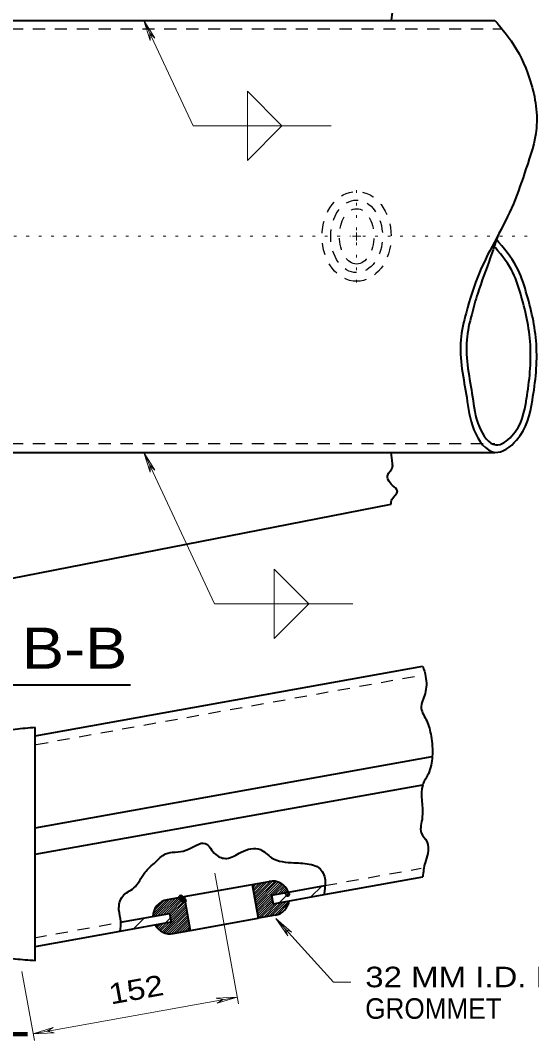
# Model space of a CAD drawing. Extents: x 312583 to 312854, y 144419 to 144597.
# Drawn here: x 312648.02 to 312666.93, y 144529.59 to 144567.31 of the extents above; entities that cross this region are included whole.
import ezdxf

# ---------------------------------------------------------------- set-up
doc = ezdxf.new("R2010")
doc.units = 0
doc.header["$LTSCALE"] = 0.3
doc.header["$PDMODE"] = 32
doc.header["$PDSIZE"] = 0.15
doc.linetypes.add('DOTTED', pattern=[1.5, 0.3, -1.2])
doc.linetypes.add('SHORT_DASHED', pattern=[2.7, 1.5, -1.2])
doc.layers.add('1', color=7, linetype='Continuous', lineweight=35)
doc.layers.add('2', color=7, linetype='Continuous', lineweight=13)

msp = doc.modelspace()

# ---------------------------------------------------------------- linework, layer by layer
at = {"layer": '1', "lineweight": 40}
for p, q in [((312647.674, 144567.3086), (312665.568, 144567.3086)), ((312647.674, 144551.3389), (312665.568, 144551.3389)), ((312647.674, 144546.6776), (312661.7347, 144549.4223)), ((312648.571, 144540.8586), (312662.9, 144543.4346)), ((312648.571, 144532.5403), (312648.571, 144541.1653)), ((312648.571, 144537.4546), (312663.2527, 144540.0919)), ((312648.571, 144536.4809), (312662.9, 144539.0493)), ((312656.5903, 144535.3616), (312657.219, 144535.4766)), ((312659.2507, 144534.9936), (312662.9, 144535.6453)), ((312654.0757, 144534.9169), (312656.5903, 144535.3616)), ((312656.5903, 144535.3616), (312656.8203, 144534.1119)), ((312657.311, 144534.9629), (312657.932, 144535.0779)), ((312657.932, 144535.0779), (312659.2813, 144535.3233)), ((312654.0757, 144534.9093), (312653.447, 144534.7943)), ((312654.0757, 144534.9169), (312654.3057, 144533.6596)), ((312657.311, 144534.9629), (312657.3723, 144534.6486)), ((312657.3723, 144534.6486), (312659.2507, 144534.9859)), ((312651.7297, 144533.9663), (312653.539, 144534.2883)), ((312653.539, 144534.2883), (312653.6003, 144533.9739)), ((312651.7067, 144533.6366), (312653.6003, 144533.9739)), ((312654.3057, 144533.6596), (312656.8203, 144534.1119)), ((312657.449, 144534.2269), (312656.8203, 144534.1119)), ((312648.571, 144533.0693), (312651.7067, 144533.6366)), ((312653.677, 144533.5446), (312654.3057, 144533.6596))]:
    msp.add_line(p, q, dxfattribs=at)
at = {"layer": '1', "linetype": 'SHORT_DASHED', "lineweight": 25}
for p, q in [((312647.674, 144566.9943), (312665.821, 144566.9943)), ((312647.674, 144551.6609), (312665.568, 144551.6609)), ((312648.6017, 144540.5366), (312662.923, 144543.1126)), ((312659.2813, 144535.3233), (312662.8387, 144535.9596)), ((312648.5403, 144533.3913), (312651.7373, 144533.9663))]:
    msp.add_line(p, q, dxfattribs=at)
at = {"layer": '1', "linetype": 'DOTTED', "lineweight": 13}
for p, q in [((312660.4543, 144559.5499), (312660.4543, 144561.0679)), ((312660.4543, 144559.0976), (312660.4543, 144557.5873))]:
    msp.add_line(p, q, dxfattribs=at)
at = {"layer": '1', "lineweight": 13}
for p, q in [((312660.4543, 144559.3276), (312660.301, 144559.3276)), ((312660.4543, 144559.3276), (312660.4543, 144559.4733)), ((312660.4543, 144559.3276), (312660.6077, 144559.3276)), ((312660.4543, 144559.3276), (312660.4543, 144559.1743)), ((312657.5947, 144534.6869), (312657.9933, 144535.0933)), ((312658.7677, 144534.9016), (312659.174, 144535.3003)), ((312652.205, 144533.7209), (312652.6037, 144534.1196)), ((312653.378, 144533.9356), (312653.5697, 144534.1273))]:
    msp.add_line(p, q, dxfattribs=at)
at = {"layer": '1'}
for p, q in [((312656.6287, 144535.1776), (312656.8587, 144535.4076)), ((312656.6363, 144535.1086), (312656.966, 144535.4306)), ((312656.6517, 144535.0319), (312657.0657, 144535.4459)), ((312656.667, 144534.9629), (312657.1653, 144535.4689)), ((312656.6747, 144534.8939), (312657.265, 144535.4843)), ((312656.69, 144534.8249), (312657.3493, 144535.4843)), ((312656.7053, 144534.7559), (312657.426, 144535.4766)), ((312656.713, 144534.6793), (312657.495, 144535.4689)), ((312656.7283, 144534.6103), (312657.5563, 144535.4459)), ((312656.7437, 144534.5413), (312657.6177, 144535.4153)), ((312656.6057, 144535.3156), (312656.6593, 144535.3769)), ((312656.6133, 144535.2466), (312656.759, 144535.3923)), ((312656.7513, 144534.4723), (312657.6713, 144535.3846)), ((312657.334, 144534.9706), (312657.7173, 144535.3539)), ((312657.6407, 144535.0243), (312657.8477, 144535.2313)), ((312657.7403, 144535.0396), (312657.8783, 144535.1853)), ((312657.84, 144535.0626), (312657.909, 144535.1239)), ((312652.9257, 144534.1886), (312653.5467, 144534.8173)), ((312652.941, 144534.2883), (312653.447, 144534.7943)), ((312652.9717, 144534.4033), (312653.3167, 144534.7483)), ((312653.01, 144534.1963), (312653.6463, 144534.8326)), ((312653.1097, 144534.2116), (312653.746, 144534.8479)), ((312653.2093, 144534.2269), (312653.8533, 144534.8709)), ((312653.309, 144534.2499), (312653.953, 144534.8863)), ((312653.4163, 144534.2653), (312654.0527, 144534.9093)), ((312653.5083, 144534.2806), (312654.0833, 144534.8556)), ((312653.5543, 144534.2423), (312654.0987, 144534.7866)), ((312653.5697, 144534.1733), (312654.1063, 144534.7176)), ((312656.7667, 144534.4033), (312657.3187, 144534.9476)), ((312656.782, 144534.3343), (312657.3263, 144534.8786)), ((312656.7897, 144534.2653), (312657.3417, 144534.8096)), ((312656.805, 144534.1886), (312657.357, 144534.7406)), ((312656.8203, 144534.1196), (312657.3647, 144534.6716)), ((312656.9047, 144534.1273), (312657.4413, 144534.6563)), ((312657.012, 144534.1426), (312657.541, 144534.6793)), ((312657.1117, 144534.1656), (312657.6483, 144534.6946)), ((312657.2113, 144534.1809), (312657.748, 144534.7176)), ((312657.311, 144534.2039), (312657.8477, 144534.7329)), ((312657.4183, 144534.2193), (312657.9473, 144534.7483)), ((312657.5333, 144534.2499), (312657.9397, 144534.6639)), ((312653.263, 144533.6136), (312654.1447, 144534.5029)), ((312653.3167, 144533.5906), (312654.16, 144534.4339)), ((312653.378, 144533.5676), (312654.1753, 144534.3649)), ((312653.4393, 144533.5446), (312654.1907, 144534.2959)), ((312653.5773, 144534.0966), (312654.1217, 144534.6409)), ((312653.5927, 144534.0276), (312654.137, 144534.5719)), ((312657.6867, 144534.3266), (312657.8707, 144534.5029)), ((312653.079, 144533.7669), (312653.217, 144533.9049)), ((312653.1173, 144533.7209), (312653.3167, 144533.9279)), ((312653.1633, 144533.6826), (312653.424, 144533.9433)), ((312653.2093, 144533.6443), (312653.5237, 144533.9586)), ((312653.5237, 144533.5446), (312654.1983, 144534.2193)), ((312653.6003, 144533.5369), (312654.2137, 144534.1503)), ((312653.6923, 144533.5523), (312654.229, 144534.0813)), ((312653.792, 144533.5676), (312654.2367, 144534.0123)), ((312653.8917, 144533.5829), (312654.252, 144533.9433)), ((312653.0023, 144533.8589), (312653.0177, 144533.8666)), ((312653.0407, 144533.8129), (312653.1173, 144533.8896)), ((312653.999, 144533.6059), (312654.2673, 144533.8666)), ((312654.0987, 144533.6213), (312654.275, 144533.7976)), ((312654.1983, 144533.6366), (312654.2903, 144533.7286)), ((312654.298, 144533.6519), (312654.298, 144533.6596))]:
    msp.add_line(p, q, dxfattribs=at)
for points in [[(312657.4337, 144534.9859), (312657.7633, 144535.3156), (312657.7633, 144535.3156)], [(312657.541, 144535.0089), (312657.8017, 144535.2773), (312657.8093, 144535.2773)]]:
    msp.add_lwpolyline(points, dxfattribs=at)
at = {"layer": '1', "lineweight": 40}
for centre, start, end in [((312657.3365, 144534.8509), 20.92751, 100.40744), ((312653.5589, 144534.1708), 99.90643, 179.34108), ((312657.3365, 144534.8509), 279.9552, 351.41104), ((312653.5589, 144534.1708), 208.60683, 280.45563)]:
    msp.add_arc(centre, 0.6361, start, end, dxfattribs=at)
at = {"layer": '1', "linetype": 'SHORT_DASHED', "lineweight": 25}
for major_axis, ratio in [((0, -1.6611), 0.769231), ((0, -1.3417), 0.714286), ((0, -1.0222), 0.625)]:
    msp.add_ellipse((312660.4543, 144559.325), major_axis=major_axis, ratio=ratio, dxfattribs=at)
at = {"layer": '1', "lineweight": 40}
for points in [[(312661.7347, 144569.2253), (312661.7577, 144569.0566), (312661.9647, 144568.7423), (312661.7807, 144568.5353), (312661.6273, 144568.3359), (312661.6043, 144568.1519), (312661.7807, 144567.8683), (312661.7807, 144567.7149), (312661.7347, 144567.3086)], [(312665.568, 144567.3086), (312666.166, 144566.5573), (312666.8407, 144565.1849), (312667.1013, 144563.3219), (312666.718, 144561.8193), (312666.2503, 144560.5313), (312665.637, 144559.2739), (312664.993, 144557.9859), (312664.5023, 144556.4909), (312664.303, 144555.5019), (312664.5253, 144553.3629), (312664.7937, 144552.1669), (312665.568, 144551.3389), (312666.373, 144551.7913), (312666.9557, 144553.2709), (312667.1013, 144555.3333), (312666.718, 144557.2883), (312666.373, 144558.1929), (312665.614, 144559.2203)], [(312665.66, 144559.3123), (312665.3993, 144558.5303), (312664.9317, 144557.2193), (312664.7093, 144556.4373), (312664.5253, 144555.4943), (312664.74, 144553.3936), (312664.993, 144552.2743), (312665.6063, 144551.6149), (312666.1967, 144551.9446), (312666.741, 144553.3169), (312666.879, 144555.3179), (312666.511, 144557.2269), (312666.1813, 144558.0856), (312665.4913, 144559.0133)], [(312661.7347, 144549.4223), (312661.7577, 144549.5986), (312661.9647, 144549.9053), (312661.7807, 144550.1123), (312661.6273, 144550.3193), (312661.6043, 144550.4956), (312661.7807, 144550.7793), (312661.7807, 144550.9326), (312661.7347, 144551.3389)], [(312662.9, 144543.4346), (312663.0073, 144543.0513), (312662.9843, 144542.4226), (312662.8463, 144541.8783), (312663.0457, 144541.4106), (312663.2067, 144540.8509), (312663.2527, 144540.0919), (312663.107, 144539.4556), (312662.9, 144539.0493), (312662.8847, 144537.8379), (312662.8463, 144537.2706), (312663.0457, 144536.9486), (312663.084, 144536.5039), (312662.9843, 144536.1589), (312662.9, 144535.6453)], [(312648.571, 144541.1653), (312647.835, 144541.0963), (312647.3827, 144541.0196), (312646.5547, 144540.5519), (312645.8877, 144539.6396), (312645.282, 144538.1676), (312645.1287, 144536.8489)], [(312651.7067, 144533.6366), (312651.7373, 144533.9893), (312651.6683, 144534.4263), (312651.8063, 144534.9323), (312652.2127, 144535.2313), (312652.6267, 144535.7986), (312653.0177, 144536.1896), (312653.3857, 144536.4886), (312654.1447, 144536.6266), (312654.8577, 144536.8796), (312655.2487, 144536.4656), (312655.655, 144536.3276), (312656.184, 144536.5576), (312656.897, 144536.6496), (312657.311, 144536.3506), (312658.139, 144536.1666), (312658.783, 144536.0976), (312659.059, 144535.9826), (312659.289, 144535.5303), (312659.2737, 144535.1929), (312659.2507, 144534.9936)], [(312648.571, 144532.5403), (312647.835, 144532.6016), (312647.3827, 144532.6859), (312646.5547, 144533.1536), (312645.8877, 144534.0583), (312645.282, 144535.5379), (312645.1287, 144536.8489)]]:
    msp.add_spline(points, degree=3, dxfattribs=at)
at = {"layer": '1'}
for p in [(312657.9013, 144535.0013), (312653.953, 144534.8863), (312653.9913, 144534.8479), (312654.0297, 144534.8019), (312654.0757, 144534.7636)]:
    msp.add_point(p, dxfattribs=at)
at = {"layer": '2'}
for p, q in [((312654.4053, 144563.4139), (312652.5807, 144567.3086)), ((312652.5807, 144567.3086), (312652.8183, 144566.5726)), ((312652.5807, 144567.3086), (312652.9947, 144566.6569)), ((312652.8183, 144566.5726), (312652.803, 144566.8333)), ((312652.9947, 144566.6569), (312652.803, 144566.8333)), ((312659.519, 144563.4139), (312654.4053, 144563.4139)), ((312655.2027, 144545.7423), (312652.5807, 144551.3389)), ((312652.5807, 144551.3389), (312652.8183, 144550.6029)), ((312652.5807, 144551.3389), (312652.9947, 144550.6796)), ((312652.8183, 144550.6029), (312652.803, 144550.8636)), ((312652.9947, 144550.6796), (312652.803, 144550.8636)), ((312660.3163, 144545.7423), (312655.2027, 144545.7423)), ((312655.2103, 144535.7833), (312656.0843, 144530.9456)), ((312657.4643, 144534.1043), (312657.909, 144533.4679)), ((312657.4643, 144534.1043), (312658.047, 144533.5983)), ((312657.909, 144533.4679), (312657.817, 144533.7133)), ((312658.047, 144533.5983), (312657.817, 144533.7133)), ((312648.0803, 144532.1416), (312648.5403, 144529.5886)), ((312648.4943, 144529.8416), (312656.0383, 144531.1986)), ((312656.0383, 144531.1986), (312655.264, 144531.1526)), ((312655.264, 144531.1526), (312655.5247, 144531.1066)), ((312656.0383, 144531.1986), (312655.2947, 144530.9686)), ((312655.2947, 144530.9686), (312655.5247, 144531.1066)), ((312648.4943, 144529.8416), (312649.2303, 144530.0716)), ((312648.4943, 144529.8416), (312649.2687, 144529.8799)), ((312649.2303, 144530.0716), (312649.008, 144529.9336)), ((312649.2687, 144529.8799), (312649.008, 144529.9336))]:
    msp.add_line(p, q, dxfattribs=at)
at = {"layer": '2', "linetype": 'DOTTED'}
for p, q in [((312637.2013, 144559.3276), (312660.232, 144559.3276)), ((312660.6843, 144559.3276), (312667.0247, 144559.3276))]:
    msp.add_line(p, q, dxfattribs=at)
at = {"layer": '2', "lineweight": 40}
msp.add_line((312636.6125, 144542.7369), (312652.0881, 144542.7369), dxfattribs=at)
at = {"layer": '2'}
for points in [[(312657.6943, 144563.4139), (312656.4217, 144564.6943), (312656.4217, 144563.4139)], [(312657.6943, 144563.4139), (312656.4217, 144562.1336), (312656.4217, 144563.4139)], [(312658.691, 144545.7423), (312657.4107, 144547.0149), (312657.4107, 144545.7423)], [(312658.691, 144545.7423), (312657.4107, 144544.4619), (312657.4107, 144545.7423)], [(312657.4643, 144534.1043), (312659.6033, 144531.7429), (312660.2397, 144531.7429)]]:
    msp.add_lwpolyline(points, dxfattribs=at)

# ---------------------------------------------------------------- texts
for s, height, width, p in [('SECTION B-B', 1.52, 1.15, (312637.0399, 144543.3362)), ('32 MM I.D. RUBBER', 0.76, 1.2, (312660.7736, 144531.5606)), ('BOTTOM CLAMP DETAIL', 1.52, 1.15, (312620.8398, 144529.7405)), ('GROMMET', 0.76, 0.95, (312660.7736, 144530.3943))]:
    msp.add_text(s, height=height, dxfattribs=dict(at, width=width)).set_placement(p)
at = {"layer": '2', "width": 1.2}
msp.add_text('152 ', height=0.76, rotation=10.29, dxfattribs=at).set_placement((312651.366, 144530.9205))

doc.saveas('drawing.dxf')
